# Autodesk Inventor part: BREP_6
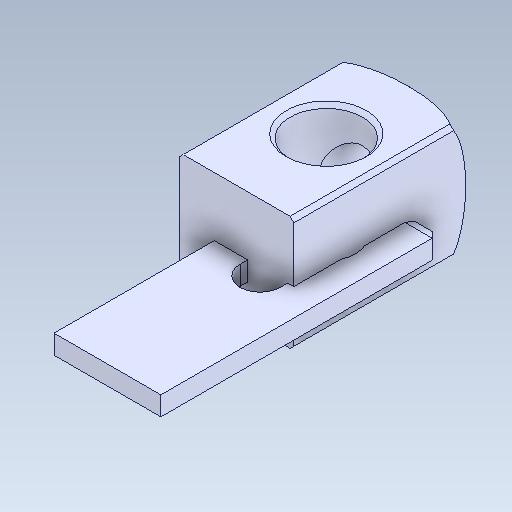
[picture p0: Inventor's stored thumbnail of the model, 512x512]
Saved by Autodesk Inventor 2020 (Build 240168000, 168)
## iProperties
Created: 2017-09
Part Number: BREP_6
Material: Générique
Document SubType Name: Modeling
Designer: bruno
Density: 1 g/cm^3
Appearance: Par défaut
Author: bruno
Sending System: SolidWorks 2016
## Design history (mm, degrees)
feature "Importée1"
node "Solide1"
